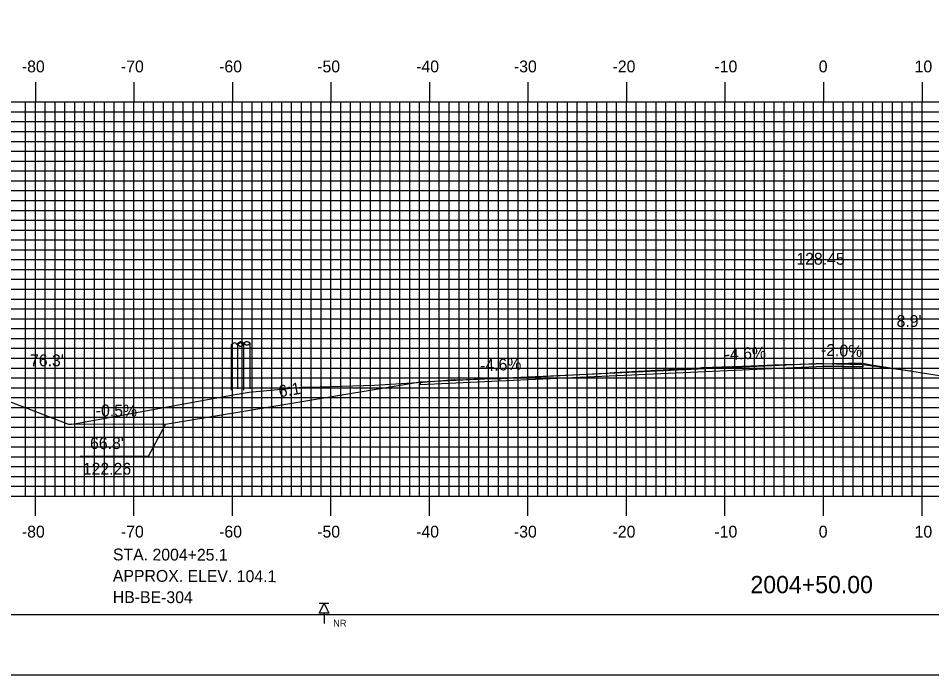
# Model space of a CAD drawing. Extents: x 851926 to 852269, y 366605 to 366825.
# Drawn here: x 852010.2 to 852103, y 366604.9 to 366671.5 of the extents above; entities that cross this region are included whole.
import ezdxf

# ---------------------------------------------------------------- set-up
doc = ezdxf.new("R2010")
doc.units = 0
for name, color, linetype in [('ANNOTATION', 7, 'Continuous'), ('BORDER', 7, 'Continuous'), ('BORING - NO REFUSAL', 7, 'Continuous'), ('D_Roadway_Centerline', 7, 'Continuous'), ('D_Roadway_Centerline_Text', 7, 'Continuous'), ('D_Roadway_Edge_Shoulder', 7, 'Continuous'), ('D_Roadway_Edge_TW', 7, 'Continuous'), ('D_Roadway_SlopeLines', 7, 'Continuous'), ('D_Text_Standard', 7, 'Continuous'), ('H_V ANNOTATION', 7, 'Continuous'), ('M_Roadway_Centerline', 7, 'Continuous'), ('M_Utilities_Pole_StreetLight', 7, 'Continuous'), ('MAJOR', 7, 'Continuous'), ('MINOR', 7, 'Continuous'), ('PLOT BOUNDARY', 7, 'Continuous'), ('S_Roadway_Centerline', 7, 'Continuous'), ('S_Utilities_Pole_StreetLight', 7, 'Continuous')]:
    doc.layers.add(name, color=color, linetype=linetype)

msp = doc.modelspace()

# ---------------------------------------------------------------- linework, layer by layer
at = {"layer": 'ANNOTATION'}
msp.add_lwpolyline([(852016.508, 366627.108), (852023.437, 366627.108), (852025.167, 366630.318)], dxfattribs=at)
at = {"layer": 'BORDER'}
msp.add_lwpolyline([(851942.365, 366611.055), (852262.365, 366611.055), (852262.365, 366821.055), (851942.365, 366821.055)], close=True, dxfattribs=at)
at = {"layer": 'BORING - NO REFUSAL'}
for p, q in [((852041.744, 366612.155), (852040.785, 366612.155)), ((852041.265, 366611.196), (852041.265, 366610.137))]:
    msp.add_line(p, q, dxfattribs=at)
msp.add_lwpolyline([(852041.265, 366612.155), (852041.744, 366611.196), (852040.785, 366611.196)], close=True, dxfattribs=at)
at = {"layer": 'D_Roadway_Centerline'}
for p, q in [((852091.964, 366636.509), (852095.964, 366636.429)), ((852091.964, 366636.259), (852095.964, 366636.179))]:
    msp.add_line(p, q, dxfattribs=at)
at = {"layer": 'D_Roadway_Edge_Shoulder'}
for points in [[(852091.964, 366636.509), (852095.964, 366636.429), (852095.964, 366636.179), (852091.964, 366636.259)], [(852059.008, 366634.993), (852051.009, 366634.625), (852051.009, 366634.375), (852059.008, 366634.743)]]:
    msp.add_lwpolyline(points, close=True, dxfattribs=at)
at = {"layer": 'D_Roadway_Edge_TW'}
for points in [[(852091.964, 366636.509), (852079.965, 366635.957), (852079.965, 366635.707), (852091.964, 366636.259)], [(852067.964, 366635.405), (852059.008, 366634.993), (852059.008, 366634.743), (852067.964, 366635.155)], [(852079.965, 366635.957), (852067.964, 366635.405), (852067.964, 366635.155), (852079.965, 366635.707)]]:
    msp.add_lwpolyline(points, close=True, dxfattribs=at)
msp.add_lwpolyline([(852067.964, 366635.155), (852067.964, 366635.405)], dxfattribs=at)
at = {"layer": 'D_Roadway_SlopeLines'}
msp.add_line((852095.964, 366636.429), (852100.819, 366635.765), dxfattribs=at)
for points in [[(852051.009, 366634.625), (852025.167, 366630.318)], [(852025.167, 366630.318), (852015.644, 366630.364)]]:
    msp.add_lwpolyline(points, dxfattribs=at)
at = {"layer": 'M_Utilities_Pole_StreetLight'}
for p, q in [((852031.867, 366633.815), (852031.864, 366638.434)), ((852031.867, 366638.434), (852032.023, 366638.545)), ((852032.336, 366638.545), (852032.492, 366638.434)), ((852032.649, 366638.545), (852032.492, 366638.434)), ((852032.492, 366638.434), (852032.649, 366638.324)), ((852033.117, 366638.434), (852032.961, 366638.545)), ((852032.961, 366638.324), (852033.117, 366638.434)), ((852033.117, 366633.815), (852033.114, 366638.434))]:
    msp.add_line(p, q, dxfattribs=at)
for centre, start, end in [((852032.18, 366638.324), 90, 125.26439), ((852032.18, 366638.324), 54.73561, 90), ((852032.805, 366638.324), 90, 125.26439), ((852032.805, 366638.545), 234.73561, 270), ((852032.805, 366638.324), 54.73561, 90), ((852032.805, 366638.545), 270, 305.26439)]:
    msp.add_arc(centre, 0.271, start, end, dxfattribs=at)
at = {"layer": 'MAJOR'}
for p, q in [((852011.965, 366665.059), (852011.965, 366663.055)), ((852021.965, 366665.059), (852021.965, 366663.055)), ((852031.965, 366665.059), (852031.965, 366663.055)), ((852041.965, 366665.059), (852041.965, 366663.055)), ((852051.965, 366665.059), (852051.965, 366663.055)), ((852061.965, 366665.059), (852061.965, 366663.055)), ((852071.965, 366665.059), (852071.965, 366663.055)), ((852081.965, 366665.059), (852081.965, 366663.055)), ((852091.965, 366665.059), (852091.965, 366663.055)), ((852101.965, 366665.059), (852101.965, 366663.055)), ((851951.965, 366663.055), (852231.965, 366663.055)), ((851951.965, 366663.055), (852231.965, 366663.055)), ((852011.965, 366623.055), (852011.965, 366663.055)), ((852021.965, 366623.055), (852021.965, 366663.055)), ((852031.965, 366623.055), (852031.965, 366663.055)), ((852041.965, 366623.055), (852041.965, 366663.055)), ((852051.965, 366623.055), (852051.965, 366663.055)), ((852061.965, 366623.055), (852061.965, 366663.055)), ((852071.965, 366623.055), (852071.965, 366663.055)), ((852081.965, 366623.055), (852081.965, 366663.055)), ((852091.965, 366623.055), (852091.965, 366663.055)), ((852101.965, 366623.055), (852101.965, 366663.055)), ((851951.965, 366658.055), (852231.965, 366658.055)), ((851951.965, 366653.055), (852231.965, 366653.055)), ((851951.965, 366648.055), (852231.965, 366648.055)), ((851951.965, 366643.055), (852231.965, 366643.055)), ((851951.965, 366638.055), (852231.965, 366638.055)), ((851951.965, 366633.055), (852231.965, 366633.055)), ((851951.965, 366628.055), (852231.965, 366628.055)), ((851951.965, 366623.055), (852231.965, 366623.055)), ((851951.965, 366623.055), (852231.965, 366623.055)), ((852011.965, 366621.051), (852011.965, 366623.055)), ((852021.965, 366621.051), (852021.965, 366623.055)), ((852031.965, 366621.051), (852031.965, 366623.055)), ((852041.965, 366621.051), (852041.965, 366623.055)), ((852051.965, 366621.051), (852051.965, 366623.055)), ((852061.965, 366621.051), (852061.965, 366623.055)), ((852071.965, 366621.051), (852071.965, 366623.055)), ((852081.965, 366621.051), (852081.965, 366623.055)), ((852091.965, 366621.051), (852091.965, 366623.055)), ((852101.965, 366621.051), (852101.965, 366623.055))]:
    msp.add_line(p, q, dxfattribs=at)
at = {"layer": 'MINOR'}
for p, q in [((852010.965, 366623.055), (852010.965, 366663.055)), ((852012.965, 366623.055), (852012.965, 366663.055)), ((852013.965, 366623.055), (852013.965, 366663.055)), ((852014.965, 366623.055), (852014.965, 366663.055)), ((852015.965, 366623.055), (852015.965, 366663.055)), ((852016.965, 366623.055), (852016.965, 366663.055)), ((852017.965, 366623.055), (852017.965, 366663.055)), ((852018.965, 366623.055), (852018.965, 366663.055)), ((852019.965, 366623.055), (852019.965, 366663.055)), ((852020.965, 366623.055), (852020.965, 366663.055)), ((852022.965, 366623.055), (852022.965, 366663.055)), ((852023.965, 366623.055), (852023.965, 366663.055)), ((852024.965, 366623.055), (852024.965, 366663.055)), ((852025.965, 366623.055), (852025.965, 366663.055)), ((852026.965, 366623.055), (852026.965, 366663.055)), ((852027.965, 366623.055), (852027.965, 366663.055)), ((852028.965, 366623.055), (852028.965, 366663.055)), ((852029.965, 366623.055), (852029.965, 366663.055)), ((852030.965, 366623.055), (852030.965, 366663.055)), ((852032.965, 366623.055), (852032.965, 366663.055)), ((852033.965, 366623.055), (852033.965, 366663.055)), ((852034.965, 366623.055), (852034.965, 366663.055)), ((852035.965, 366623.055), (852035.965, 366663.055)), ((852036.965, 366623.055), (852036.965, 366663.055)), ((852037.965, 366623.055), (852037.965, 366663.055)), ((852038.965, 366623.055), (852038.965, 366663.055)), ((852039.965, 366623.055), (852039.965, 366663.055)), ((852040.965, 366623.055), (852040.965, 366663.055)), ((852042.965, 366623.055), (852042.965, 366663.055)), ((852043.965, 366623.055), (852043.965, 366663.055)), ((852044.965, 366623.055), (852044.965, 366663.055)), ((852045.965, 366623.055), (852045.965, 366663.055)), ((852046.965, 366623.055), (852046.965, 366663.055)), ((852047.965, 366623.055), (852047.965, 366663.055)), ((852048.965, 366623.055), (852048.965, 366663.055)), ((852049.965, 366623.055), (852049.965, 366663.055)), ((852050.965, 366623.055), (852050.965, 366663.055)), ((852052.965, 366623.055), (852052.965, 366663.055)), ((852053.965, 366623.055), (852053.965, 366663.055)), ((852054.965, 366623.055), (852054.965, 366663.055)), ((852055.965, 366623.055), (852055.965, 366663.055)), ((852056.965, 366623.055), (852056.965, 366663.055)), ((852057.965, 366623.055), (852057.965, 366663.055)), ((852058.965, 366623.055), (852058.965, 366663.055)), ((852059.965, 366623.055), (852059.965, 366663.055)), ((852060.965, 366623.055), (852060.965, 366663.055)), ((852062.965, 366623.055), (852062.965, 366663.055)), ((852063.965, 366623.055), (852063.965, 366663.055)), ((852064.965, 366623.055), (852064.965, 366663.055)), ((852065.965, 366623.055), (852065.965, 366663.055)), ((852066.965, 366623.055), (852066.965, 366663.055)), ((852067.965, 366623.055), (852067.965, 366663.055)), ((852068.965, 366623.055), (852068.965, 366663.055)), ((852069.965, 366623.055), (852069.965, 366663.055)), ((852070.965, 366623.055), (852070.965, 366663.055)), ((852072.965, 366623.055), (852072.965, 366663.055)), ((852073.965, 366623.055), (852073.965, 366663.055)), ((852074.965, 366623.055), (852074.965, 366663.055)), ((852075.965, 366623.055), (852075.965, 366663.055)), ((852076.965, 366623.055), (852076.965, 366663.055)), ((852077.965, 366623.055), (852077.965, 366663.055)), ((852078.965, 366623.055), (852078.965, 366663.055)), ((852079.965, 366623.055), (852079.965, 366663.055)), ((852080.965, 366623.055), (852080.965, 366663.055)), ((852082.965, 366623.055), (852082.965, 366663.055)), ((852083.965, 366623.055), (852083.965, 366663.055)), ((852084.965, 366623.055), (852084.965, 366663.055)), ((852085.965, 366623.055), (852085.965, 366663.055)), ((852086.965, 366623.055), (852086.965, 366663.055)), ((852087.965, 366623.055), (852087.965, 366663.055)), ((852088.965, 366623.055), (852088.965, 366663.055)), ((852089.965, 366623.055), (852089.965, 366663.055)), ((852090.965, 366623.055), (852090.965, 366663.055)), ((852092.965, 366623.055), (852092.965, 366663.055)), ((852093.965, 366623.055), (852093.965, 366663.055)), ((852094.965, 366623.055), (852094.965, 366663.055)), ((852095.965, 366623.055), (852095.965, 366663.055)), ((852096.965, 366623.055), (852096.965, 366663.055)), ((852097.965, 366623.055), (852097.965, 366663.055)), ((852098.965, 366623.055), (852098.965, 366663.055)), ((852099.965, 366623.055), (852099.965, 366663.055)), ((852100.965, 366623.055), (852100.965, 366663.055)), ((851951.965, 366662.055), (852231.965, 366662.055)), ((851951.965, 366661.055), (852231.965, 366661.055)), ((851951.965, 366660.055), (852231.965, 366660.055)), ((851951.965, 366659.055), (852231.965, 366659.055)), ((851951.965, 366657.055), (852231.965, 366657.055)), ((851951.965, 366656.055), (852231.965, 366656.055)), ((851951.965, 366655.055), (852231.965, 366655.055)), ((851951.965, 366654.055), (852231.965, 366654.055)), ((851951.965, 366652.055), (852231.965, 366652.055)), ((851951.965, 366651.055), (852231.965, 366651.055)), ((851951.965, 366650.055), (852231.965, 366650.055)), ((851951.965, 366649.055), (852231.965, 366649.055)), ((851951.965, 366647.055), (852231.965, 366647.055)), ((851951.965, 366646.055), (852231.965, 366646.055)), ((851951.965, 366645.055), (852231.965, 366645.055)), ((851951.965, 366644.055), (852231.965, 366644.055)), ((851951.965, 366642.055), (852231.965, 366642.055)), ((851951.965, 366641.055), (852231.965, 366641.055)), ((851951.965, 366640.055), (852231.965, 366640.055)), ((851951.965, 366639.055), (852231.965, 366639.055)), ((851951.965, 366637.055), (852231.965, 366637.055)), ((851951.965, 366636.055), (852231.965, 366636.055)), ((851951.965, 366635.055), (852231.965, 366635.055)), ((851951.965, 366634.055), (852231.965, 366634.055)), ((851951.965, 366632.055), (852231.965, 366632.055)), ((851951.965, 366631.055), (852231.965, 366631.055)), ((851951.965, 366630.055), (852231.965, 366630.055)), ((851951.965, 366629.055), (852231.965, 366629.055)), ((851951.965, 366627.055), (852231.965, 366627.055)), ((851951.965, 366626.055), (852231.965, 366626.055)), ((851951.965, 366625.055), (852231.965, 366625.055)), ((851951.965, 366624.055), (852231.965, 366624.055))]:
    msp.add_line(p, q, dxfattribs=at)
at = {"layer": 'PLOT BOUNDARY'}
msp.add_lwpolyline([(851926.178, 366604.937), (852266.178, 366604.937), (852266.178, 366824.937), (851926.178, 366824.937)], close=True, dxfattribs=at)
at = {"layer": 'S_Roadway_Centerline'}
msp.add_lwpolyline([(852005.693, 366634.033), (852015.316, 366630.358), (852015.644, 366630.364), (852016.112, 366630.435), (852032.04, 366633.32), (852033.474, 366633.573), (852033.672, 366633.611), (852039.069, 366634.107), (852039.761, 366634.113), (852046.373, 366634.314), (852051.273, 366634.615), (852054.544, 366634.875), (852054.913, 366634.866), (852058.032, 366635.007), (852058.649, 366634.964), (852069.838, 366635.544), (852070.708, 366635.588), (852079.401, 366636.069), (852079.612, 366636.113), (852083.728, 366636.256), (852087.888, 366636.413), (852094.492, 366636.559), (852095.957, 366636.533), (852096.802, 366636.388), (852104.837, 366635.142)], dxfattribs=at)
at = {"layer": 'S_Utilities_Pole_StreetLight'}
for p, q in [((852032.514, 366633.943), (852032.511, 366638.563)), ((852032.514, 366638.563), (852032.67, 366638.673)), ((852032.982, 366638.673), (852033.139, 366638.563)), ((852033.295, 366638.673), (852033.139, 366638.563)), ((852033.139, 366638.563), (852033.295, 366638.452)), ((852033.764, 366638.563), (852033.608, 366638.673)), ((852033.608, 366638.452), (852033.764, 366638.563)), ((852033.764, 366633.943), (852033.761, 366638.563))]:
    msp.add_line(p, q, dxfattribs=at)
for centre, start, end in [((852032.826, 366638.452), 90, 125.26439), ((852032.826, 366638.452), 54.73561, 90), ((852033.451, 366638.452), 90, 125.26439), ((852033.451, 366638.673), 234.73561, 270), ((852033.451, 366638.452), 54.73561, 90), ((852033.451, 366638.673), 270, 305.26439)]:
    msp.add_arc(centre, 0.271, start, end, dxfattribs=at)

# ---------------------------------------------------------------- texts
at = {"layer": 'ANNOTATION'}
for s, rotation, p in [('-4.6%', 2.63385, (852081.963, 366636.851)), ('-2.0%', 357.70983, (852091.687, 366637.322)), ('-4.6%', 2.63388, (852057.127, 366635.709)), ('6:1', 9.46241, (852036.758, 366633.078)), ('-0.5%', 359.72326, (852018.092, 366631.152)), ("66.8' ", 360, (852017.512, 366627.834)), ('122.26', 360, (852016.778, 366625.234))]:
    msp.add_text(s, height=1.2, rotation=rotation, dxfattribs=at).set_placement(p)
at = {"layer": 'BORING - NO REFUSAL'}
for s, p in [('STA. 2004+25.1', (852019.836, 366616.541)), ('APPROX. ELEV. 104.1', (852019.829, 366614.381)), ('HB-BE-304', (852019.822, 366612.221))]:
    msp.add_text(s, height=1.2, rotation=359.81416, dxfattribs=at).set_placement(p)
msp.add_text('NR', height=0.6998, dxfattribs=at).set_placement((852042.197, 366609.816))
at = {"layer": 'D_Roadway_Centerline_Text'}
msp.add_text('128.45', height=1.2, dxfattribs=at).set_placement((852089.209, 366646.539))
at = {"layer": 'D_Text_Standard'}
for s, p in [("8.9'", (852099.385, 366640.226)), ("76.3'", (852011.419, 366636.233))]:
    msp.add_text(s, height=1.2, dxfattribs=at).set_placement(p)
at = {"layer": 'H_V ANNOTATION'}
for s, height, p in [('-80', 1.2, (852010.594, 366666.055)), ('-70', 1.2, (852020.648, 366666.055)), ('-60', 1.2, (852030.616, 366666.055)), ('-50', 1.2, (852040.573, 366666.055)), ('-40', 1.2, (852050.616, 366666.055)), ('-30', 1.2, (852060.541, 366666.055)), ('-20', 1.2, (852070.552, 366666.055)), ('-10', 1.2, (852080.894, 366666.055)), ('0', 1.2, (852091.483, 366666.055)), ('10', 1.2, (852101.215, 366666.055)), ('-80', 1.2, (852010.594, 366618.855)), ('-70', 1.2, (852020.648, 366618.855)), ('-60', 1.2, (852030.616, 366618.855)), ('-50', 1.2, (852040.573, 366618.855)), ('-40', 1.2, (852050.616, 366618.855)), ('-30', 1.2, (852060.541, 366618.855)), ('-20', 1.2, (852070.552, 366618.855)), ('-10', 1.2, (852080.894, 366618.855)), ('0', 1.2, (852091.483, 366618.855)), ('10', 1.2, (852101.215, 366618.855)), ('2004+50.00', 1.75, (852084.551, 366613.211))]:
    msp.add_text(s, height=height, dxfattribs=at).set_placement(p)
at = {"layer": 'M_Roadway_Centerline'}
for s, p in [('C', (852079.607, 366636.113)), ('L', (852079.612, 366636.106)), ('C', (852054.538, 366634.875)), ('L', (852054.544, 366634.868))]:
    msp.add_text(s, height=0.0146, dxfattribs=at).set_placement(p)

doc.saveas('drawing.dxf')
